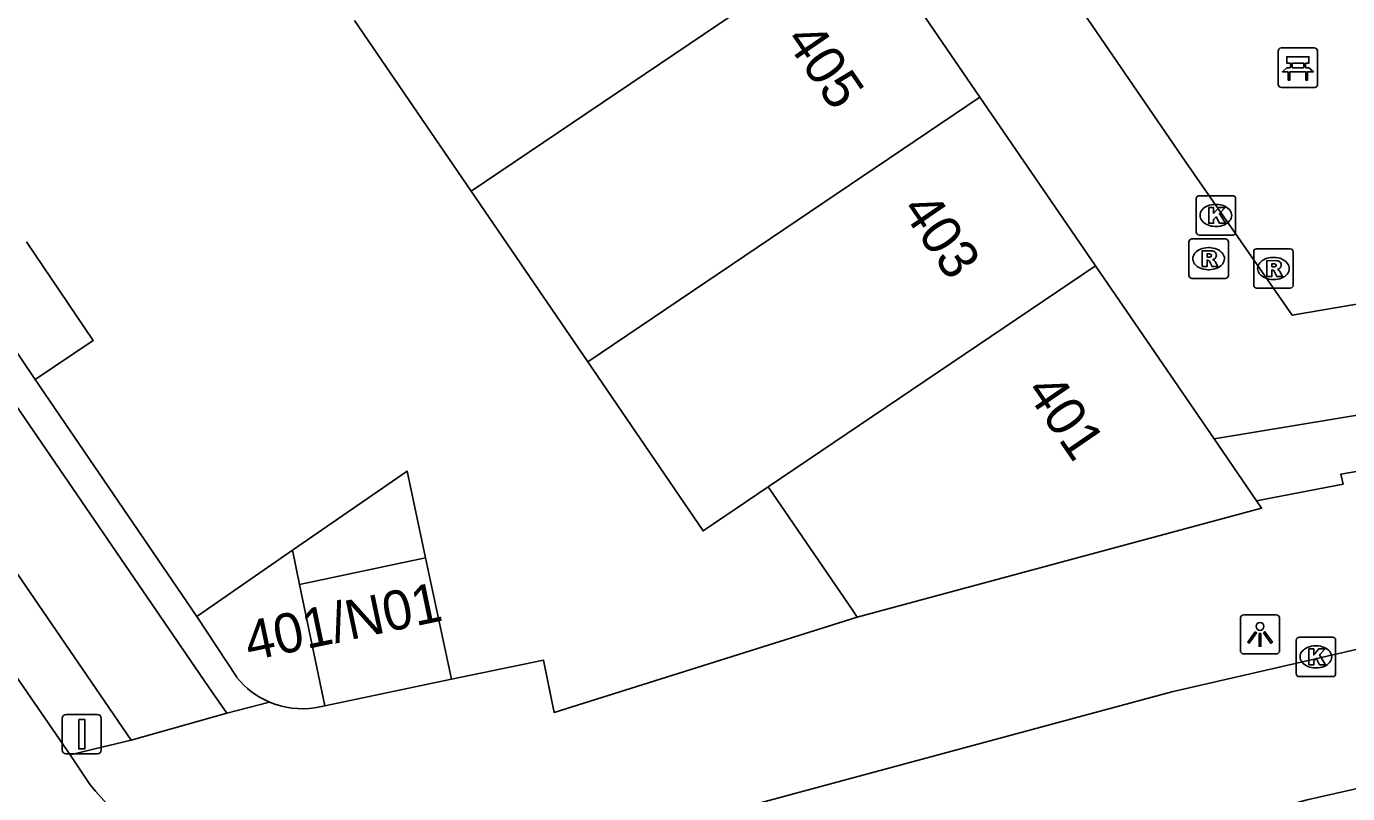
# Model space of a CAD drawing. Extents: x 155275 to 156263, y 382654 to 383635.
# Drawn here: x 155741.8 to 155775.32, y 383184.9 to 383204.38 of the extents above; entities that cross this region are included whole.
import ezdxf

# ---------------------------------------------------------------- set-up
doc = ezdxf.new("R2010")
doc.units = 0
for name, color, linetype in [('IMGEO_Bank', 7, 'Continuous'), ('IMGEO_Hek', 7, 'Continuous'), ('IMGEO_Kolk', 7, 'Continuous'), ('IMGEO_Lichtpunt', 7, 'Continuous'), ('IMGEO_Pand', 7, 'Continuous'), ('IMGEO_Pand_nummerreeks', 7, 'Continuous'), ('IMGEO_Rijbaan_lokaal_gesloten', 7, 'Continuous'), ('IMGEO_Rijbaan_lokaal_open', 7, 'Continuous'), ('IMGEO_Rioolput', 7, 'Continuous'), ('IMGEO_Verkeersbordpaal', 7, 'Continuous'), ('IMGEO_Voetpad_open', 7, 'Continuous')]:
    doc.layers.add(name, color=color, linetype=linetype)

msp = doc.modelspace()

# ---------------------------------------------------------------- linework, layer by layer
at = {"layer": 'IMGEO_Bank'}
for p, q in [((155773.564, 383202.906), (155773.564, 383203.747)), ((155773.564, 383203.747), (155773.564, 383202.906)), ((155773.639, 383203.831), (155774.48, 383203.831)), ((155774.48, 383203.831), (155773.639, 383203.831)), ((155774.564, 383203.756), (155774.564, 383202.915)), ((155774.564, 383202.915), (155774.564, 383203.756)), ((155773.873, 383203.337), (155773.873, 383203.443)), ((155773.917, 383203.443), (155773.917, 383203.337)), ((155774.205, 383203.449), (155773.923, 383203.449)), ((155774.211, 383203.337), (155774.211, 383203.443)), ((155774.255, 383203.443), (155774.255, 383203.337)), ((155774.261, 383203.229), (155773.868, 383203.229)), ((155773.923, 383203.331), (155774.205, 383203.331)), ((155774.489, 383202.831), (155773.648, 383202.831)), ((155773.648, 383202.831), (155774.489, 383202.831))]:
    msp.add_line(p, q, dxfattribs=at)
for points in [[(155773.867, 383203.449), (155773.781, 383203.449), (155773.781, 383203.61), (155774.344, 383203.61), (155774.344, 383203.449), (155774.261, 383203.449)], [(155773.811, 383203.229), (155773.669, 383203.229), (155773.781, 383203.331), (155773.867, 383203.331)], [(155773.861, 383203.222), (155773.861, 383203.015), (155773.818, 383203.015), (155773.818, 383203.222)], [(155774.261, 383203.331), (155774.344, 383203.331), (155774.456, 383203.229), (155774.317, 383203.229)], [(155774.311, 383203.222), (155774.311, 383203.015), (155774.267, 383203.015), (155774.267, 383203.222)]]:
    msp.add_lwpolyline(points, dxfattribs=at)
for centre, radius, start, end in [((155773.642, 383203.753), 0.0779, 92.4484, 184.2845), ((155773.642, 383203.753), 0.0779, 92.4484, 184.2845), ((155774.486, 383203.753), 0.0779, 2.4484, 94.2845), ((155774.486, 383203.753), 0.0779, 2.4484, 94.2845), ((155773.866, 383203.442), 0.00671, 2.8957, 87.1043), ((155773.923, 383203.442), 0.00671, 92.8957, 177.1043), ((155774.205, 383203.442), 0.00671, 2.8957, 87.1043), ((155774.262, 383203.442), 0.00671, 92.8957, 177.1043), ((155773.811, 383203.222), 0.00671, 2.8957, 87.1043), ((155773.868, 383203.222), 0.00671, 92.8957, 177.1043), ((155773.866, 383203.338), 0.00671, 272.8957, 357.1043), ((155773.923, 383203.338), 0.00671, 182.8957, 267.1043), ((155774.205, 383203.338), 0.00671, 272.8957, 357.1043), ((155774.262, 383203.338), 0.00671, 182.8957, 267.1043), ((155774.26, 383203.222), 0.00671, 2.8957, 87.1043), ((155774.317, 383203.222), 0.00671, 92.8957, 177.1043), ((155773.642, 383202.909), 0.0779, 182.4484, 274.2845), ((155773.642, 383202.909), 0.0779, 182.4484, 274.2845), ((155774.486, 383202.909), 0.0779, 272.4484, 4.2845), ((155774.486, 383202.909), 0.0779, 272.4484, 4.2845)]:
    msp.add_arc(centre, radius, start, end, dxfattribs=at)
at = {"layer": 'IMGEO_Hek'}
for points in [[(155746.127, 383189.4), (155742.029, 383195.414)], [(155755.153, 383187.161), (155754.924, 383188.287), (155752.587, 383187.808)]]:
    msp.add_lwpolyline(points, dxfattribs=at)
at = {"layer": 'IMGEO_Kolk'}
for p, q in [((155771.557, 383200.08), (155772.409, 383200.08)), ((155771.482, 383199.154), (155771.482, 383200.006)), ((155771.97, 383199.86), (155771.995, 383199.86)), ((155772.483, 383200.006), (155772.483, 383199.154)), ((155772.409, 383199.08), (155771.557, 383199.08)), ((155771.993, 383199.3), (155771.968, 383199.3)), ((155774.02, 383187.946), (155774.02, 383188.798)), ((155774.095, 383188.872), (155774.947, 383188.872)), ((155774.508, 383188.652), (155774.533, 383188.652)), ((155775.021, 383188.798), (155775.021, 383187.946)), ((155774.531, 383188.092), (155774.506, 383188.092)), ((155774.947, 383187.872), (155774.095, 383187.872))]:
    msp.add_line(p, q, dxfattribs=at)
for points in [[(155771.557, 383200.08), (155772.409, 383200.08)], [(155771.482, 383199.154), (155771.482, 383200.006)], [(155771.803, 383199.78), (155771.926, 383199.78), (155771.926, 383199.629), (155772.056, 383199.78), (155772.22, 383199.78), (155772.074, 383199.629), (155772.227, 383199.38), (155772.075, 383199.38), (155771.99, 383199.544), (155771.926, 383199.477), (155771.926, 383199.38), (155771.803, 383199.38), (155771.803, 383199.78)], [(155772.483, 383200.006), (155772.483, 383199.154)], [(155772.409, 383199.08), (155771.557, 383199.08)], [(155774.02, 383187.946), (155774.02, 383188.798)], [(155774.095, 383188.872), (155774.947, 383188.872)], [(155775.021, 383188.798), (155775.021, 383187.946)], [(155774.341, 383188.572), (155774.464, 383188.572), (155774.464, 383188.421), (155774.594, 383188.572), (155774.758, 383188.572), (155774.612, 383188.421), (155774.765, 383188.172), (155774.613, 383188.172), (155774.528, 383188.336), (155774.464, 383188.269), (155774.464, 383188.172), (155774.341, 383188.172), (155774.341, 383188.572)], [(155774.947, 383187.872), (155774.095, 383187.872)]]:
    msp.add_lwpolyline(points, dxfattribs=at)
for centre, start, end in [((155771.559, 383200.004), 91.552, 178.448), ((155771.559, 383200.004), 91.552, 178.448), ((155772.407, 383200.004), 1.552, 88.448), ((155772.407, 383200.004), 1.552, 88.448), ((155771.559, 383199.156), 181.552, 268.448), ((155771.559, 383199.156), 181.552, 268.448), ((155772.407, 383199.156), 271.552, 358.448), ((155772.407, 383199.156), 271.552, 358.448), ((155774.097, 383188.796), 91.552, 178.448), ((155774.097, 383188.796), 91.552, 178.448), ((155774.945, 383188.796), 1.552, 88.448), ((155774.945, 383188.796), 1.552, 88.448), ((155774.097, 383187.948), 181.552, 268.448), ((155774.097, 383187.948), 181.552, 268.448), ((155774.945, 383187.948), 271.552, 358.448), ((155774.945, 383187.948), 271.552, 358.448)]:
    msp.add_arc(centre, 0.0765, start, end, dxfattribs=at)
for centre, major_axis, ratio, start_param, end_param in [((155771.969, 383199.58), (-0.387, 0.002), 0.722429, 4.712389, 7.853982), ((155771.994, 383199.58), (-0.39, 0.002), 0.717154, 1.570796, 4.712389), ((155774.507, 383188.372), (-0.387, 0.002), 0.722429, 4.712389, 7.853982), ((155774.532, 383188.372), (-0.39, 0.002), 0.717154, 1.570796, 4.712389)]:
    msp.add_ellipse(centre, major_axis=major_axis, ratio=ratio, start_param=start_param, end_param=end_param, dxfattribs=at)
at = {"layer": 'IMGEO_Lichtpunt'}
for p, q in [((155772.604, 383189.347), (155772.604, 383188.54)), ((155772.604, 383189.347), (155772.604, 383188.54)), ((155773.506, 383189.442), (155772.698, 383189.442)), ((155773.506, 383189.442), (155772.698, 383189.442)), ((155773.6, 383188.54), (155773.6, 383189.347)), ((155773.6, 383188.54), (155773.6, 383189.347)), ((155772.698, 383188.446), (155773.506, 383188.446)), ((155772.698, 383188.446), (155773.506, 383188.446))]:
    msp.add_line(p, q, dxfattribs=at)
for points in [[(155772.978, 383189.011), (155773.017, 383188.983), (155772.829, 383188.721), (155772.791, 383188.748), (155772.978, 383189.011)], [(155773.19, 383188.983), (155773.228, 383189.01), (155773.415, 383188.748), (155773.376, 383188.72), (155773.19, 383188.983)], [(155773.08, 383188.963), (155773.127, 383188.963), (155773.127, 383188.641), (155773.08, 383188.641), (155773.08, 383188.963)]]:
    msp.add_lwpolyline(points, dxfattribs=at)
msp.add_circle((155773.103, 383189.145), 0.0994, dxfattribs=at)
for centre, start, end in [((155772.698, 383189.347), 90, 180), ((155772.698, 383189.347), 90, 180), ((155773.506, 383189.347), 0, 90), ((155773.506, 383189.347), 0, 90), ((155772.698, 383188.54), 180, 270), ((155772.698, 383188.54), 180, 270), ((155773.506, 383188.54), 270, 0), ((155773.506, 383188.54), 270, 360)]:
    msp.add_arc(centre, 0.0946, start, end, dxfattribs=at)
at = {"layer": 'IMGEO_Pand'}
for points in [[(155763.031, 383206.917), (155753.088, 383200.196)], [(155765.996, 383202.584), (155763.031, 383206.917)], [(155753.088, 383200.196), (155750.129, 383204.533)], [(155756.046, 383195.859), (155765.996, 383202.584)], [(155765.996, 383202.584), (155768.927, 383198.302)], [(155756.046, 383195.859), (155753.088, 383200.196)], [(155741.803, 383198.906), (155743.494, 383196.404), (155742.029, 383195.414), (155740.338, 383197.916)], [(155760.622, 383192.689), (155768.927, 383198.302)], [(155768.927, 383198.302), (155771.936, 383193.905)], [(155760.622, 383192.689), (155758.971, 383191.572), (155756.046, 383195.859)], [(155771.936, 383193.905), (155773.013, 383192.332)], [(155748.554, 383191.079), (155751.463, 383193.091), (155751.932, 383190.889)], [(155762.885, 383189.376), (155762.768, 383189.548), (155760.622, 383192.689)], [(155773.013, 383192.332), (155773.14, 383192.147), (155762.885, 383189.376)], [(155747.138, 383187.855), (155746.127, 383189.4), (155748.554, 383191.079)], [(155748.554, 383191.079), (155748.734, 383190.211)], [(155751.932, 383190.889), (155748.734, 383190.211)], [(155751.932, 383190.889), (155752.587, 383187.808)], [(155748.734, 383190.211), (155749.371, 383187.133)], [(155752.587, 383187.808), (155749.371, 383187.133)], [(155749.371, 383187.133), (155749.124, 383187.081)]]:
    msp.add_lwpolyline(points, dxfattribs=at)
for centre, radius, start, end in [((155748.789, 383189.17), 2.111, 218.5225, 247.1894), ((155748.798, 383189.175), 2.119, 247.0195, 278.8406)]:
    msp.add_arc(centre, radius, start, end, dxfattribs=at)
at = {"layer": 'IMGEO_Rijbaan_lokaal_gesloten'}
for points in [[(155742.91, 383185.882), (155726.923, 383209.144), (155718.824, 383220.994), (155662.23, 383303.795)], [(155752.173, 383182.442), (155761.516, 383184.966), (155770.862, 383187.481), (155778.526, 383189.242), (155786.191, 383190.995)], [(155752.351, 383178.024), (155758.269, 383180.313), (155766.281, 383182.536), (155774.297, 383184.74), (155780.617, 383186.169), (155786.939, 383187.587)], [(155742.91, 383185.882), (155743.419, 383185.124)]]:
    msp.add_lwpolyline(points, dxfattribs=at)
msp.add_arc((155749.81, 383190.357), 8.26, 219.3066, 266.5965, dxfattribs=at)
at = {"layer": 'IMGEO_Rijbaan_lokaal_open'}
msp.add_lwpolyline([(155817.087, 383320.059), (155811.131, 383312.082), (155798.256, 383294.644), (155789.533, 383282.828), (155777.762, 383266.885), (155770.477, 383257.018), (155750.942, 383230.559), (155753.136, 383227.355), (155767.095, 383206.967), (155771.224, 383200.936), (155773.915, 383197.049), (155790.895, 383199.943), (155792.328, 383200.159), (155792.43, 383196.787)], dxfattribs=at)
at = {"layer": 'IMGEO_Rioolput'}
for p, q in [((155771.298, 383198.056), (155771.298, 383198.908)), ((155771.373, 383198.982), (155772.225, 383198.982)), ((155771.786, 383198.762), (155771.811, 383198.762)), ((155772.299, 383198.908), (155772.299, 383198.056)), ((155773.017, 383198.733), (155773.869, 383198.733)), ((155772.942, 383197.807), (155772.942, 383198.659)), ((155773.43, 383198.513), (155773.455, 383198.513)), ((155773.943, 383198.659), (155773.943, 383197.807)), ((155771.809, 383198.202), (155771.784, 383198.202)), ((155772.225, 383197.982), (155771.373, 383197.982)), ((155773.869, 383197.733), (155773.017, 383197.733)), ((155773.453, 383197.953), (155773.428, 383197.953))]:
    msp.add_line(p, q, dxfattribs=at)
for points in [[(155771.298, 383198.056), (155771.298, 383198.908)], [(155771.373, 383198.982), (155772.225, 383198.982)], [(155772.299, 383198.908), (155772.299, 383198.056)], [(155773.017, 383198.733), (155773.869, 383198.733)], [(155771.887, 383198.68), (155771.635, 383198.682), (155771.635, 383198.282)], [(155771.635, 383198.282), (155771.759, 383198.282), (155771.759, 383198.444), (155771.77, 383198.444)], [(155771.813, 383198.601), (155771.759, 383198.601), (155771.759, 383198.52)], [(155771.759, 383198.52), (155771.811, 383198.52)], [(155771.817, 383198.415), (155771.888, 383198.282), (155772.028, 383198.282), (155771.963, 383198.408)], [(155772.942, 383197.807), (155772.942, 383198.659)], [(155773.531, 383198.431), (155773.279, 383198.433), (155773.279, 383198.033)], [(155773.943, 383198.659), (155773.943, 383197.807)], [(155773.279, 383198.033), (155773.403, 383198.033), (155773.403, 383198.195), (155773.414, 383198.195)], [(155773.457, 383198.352), (155773.403, 383198.352), (155773.403, 383198.271)], [(155773.403, 383198.271), (155773.455, 383198.271)], [(155773.461, 383198.166), (155773.532, 383198.033), (155773.672, 383198.033), (155773.607, 383198.159)], [(155772.225, 383197.982), (155771.373, 383197.982)], [(155773.869, 383197.733), (155773.017, 383197.733)]]:
    msp.add_lwpolyline(points, dxfattribs=at)
for centre, radius, start, end in [((155771.375, 383198.906), 0.0765, 91.552, 178.448), ((155771.375, 383198.906), 0.0765, 91.552, 178.448), ((155772.223, 383198.906), 0.0765, 1.552, 88.448), ((155772.223, 383198.906), 0.0765, 1.552, 88.448), ((155773.019, 383198.657), 0.0765, 91.552, 178.448), ((155773.019, 383198.657), 0.0765, 91.552, 178.448), ((155773.867, 383198.657), 0.0765, 1.552, 88.448), ((155773.867, 383198.657), 0.0765, 1.552, 88.448), ((155771.769, 383198.391), 0.0533, 26.0293, 88.6989), ((155771.795, 383198.709), 0.19, 274.7715, 282.9687), ((155771.819, 383198.505), 0.0964, 77.0061, 93.1865), ((155771.833, 383198.562), 0.0378, 276.6634, 79.6772), ((155771.886, 383198.57), 0.109, 350.3612, 89.416), ((155771.884, 383198.57), 0.112, 277.5842, 350.9817), ((155771.868, 383198.355), 0.108, 29.5134, 73.7905), ((155773.53, 383198.321), 0.109, 350.3612, 89.416), ((155771.375, 383198.058), 0.0765, 181.552, 268.448), ((155771.375, 383198.058), 0.0765, 181.552, 268.448), ((155772.223, 383198.058), 0.0765, 271.552, 358.448), ((155772.223, 383198.058), 0.0765, 271.552, 358.448), ((155773.413, 383198.142), 0.0533, 26.0293, 88.6989), ((155773.439, 383198.46), 0.19, 274.7715, 282.9687), ((155773.463, 383198.256), 0.0964, 77.0061, 93.1865), ((155773.477, 383198.313), 0.0378, 276.6634, 79.6772), ((155773.528, 383198.321), 0.112, 277.5842, 350.9817), ((155773.512, 383198.106), 0.108, 29.5134, 73.7905), ((155773.019, 383197.809), 0.0765, 181.552, 268.448), ((155773.019, 383197.809), 0.0765, 181.552, 268.448), ((155773.867, 383197.809), 0.0765, 271.552, 358.448), ((155773.867, 383197.809), 0.0765, 271.552, 358.448)]:
    msp.add_arc(centre, radius, start, end, dxfattribs=at)
for centre, major_axis, ratio, start_param, end_param in [((155771.785, 383198.482), (-0.387, 0.002), 0.722429, 4.712389, 7.853982), ((155771.81, 383198.482), (-0.39, 0.002), 0.717154, 1.570796, 4.712389), ((155773.429, 383198.233), (-0.387, 0.002), 0.722429, 4.712389, 7.853982), ((155773.454, 383198.233), (-0.39, 0.002), 0.717154, 1.570796, 4.712389)]:
    msp.add_ellipse(centre, major_axis=major_axis, ratio=ratio, start_param=start_param, end_param=end_param, dxfattribs=at)
at = {"layer": 'IMGEO_Verkeersbordpaal'}
for p, q in [((155742.712, 383186.009), (155742.712, 383186.809)), ((155742.712, 383186.809), (155742.712, 383186.009)), ((155742.812, 383186.909), (155743.602, 383186.909)), ((155743.602, 383186.909), (155742.812, 383186.909)), ((155743.702, 383186.809), (155743.702, 383186.009)), ((155743.702, 383186.009), (155743.702, 383186.809)), ((155743.602, 383185.909), (155742.812, 383185.909)), ((155742.812, 383185.909), (155743.602, 383185.909))]:
    msp.add_line(p, q, dxfattribs=at)
msp.add_lwpolyline([(155743.132, 383186.784), (155743.282, 383186.784), (155743.282, 383186.034), (155743.132, 383186.034), (155743.132, 383186.784)], dxfattribs=at)
for centre, start, end in [((155742.812, 383186.809), 90, 180), ((155742.812, 383186.809), 90, 180), ((155743.602, 383186.809), 0, 90), ((155743.602, 383186.809), 360, 90), ((155742.812, 383186.009), 180, 270), ((155742.812, 383186.009), 180, 270), ((155743.602, 383186.009), 270, 0), ((155743.602, 383186.009), 270, 0)]:
    msp.add_arc(centre, 0.1, start, end, dxfattribs=at)
at = {"layer": 'IMGEO_Voetpad_open'}
for points in [[(155661.788, 383311.41), (155661.818, 383311.37), (155722.08, 383223.219), (155746.422, 383187.612), (155746.888, 383186.944)], [(155660.2, 383309.537), (155661.229, 383308.029), (155720.116, 383221.876), (155744.463, 383186.256)], [(155771.936, 383193.905), (155790.308, 383196.944), (155790.405, 383196.458)], [(155790.405, 383196.458), (155790.411, 383196.43), (155785.955, 383195.688), (155786.008, 383195.413), (155782.535, 383194.838), (155782.598, 383194.561), (155779.154, 383193.982), (155779.197, 383193.704), (155775.154, 383193.012), (155775.211, 383192.757), (155773.013, 383192.332)], [(155752.587, 383187.808), (155754.924, 383188.287), (155755.193, 383186.963), (155762.885, 383189.376)], [(155746.888, 383186.944), (155747.971, 383187.224)], [(155746.888, 383186.944), (155744.463, 383186.256)], [(155744.463, 383186.256), (155743.508, 383186.026), (155742.91, 383185.882)]]:
    msp.add_lwpolyline(points, dxfattribs=at)

# ---------------------------------------------------------------- texts
at = {"layer": 'IMGEO_Pand_nummerreeks'}
for s, rotation, p in [('405', 304.3888, (155761.03, 383204.033)), ('403', 304.3888, (155763.978, 383199.725)), ('401', 304.3888, (155767.13, 383195.12)), ('401/N01', 11.8545, (155747.458, 383188.264))]:
    msp.add_text(s, height=1, rotation=rotation, dxfattribs=at).set_placement(p)

doc.saveas('drawing.dxf')
